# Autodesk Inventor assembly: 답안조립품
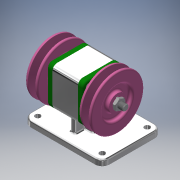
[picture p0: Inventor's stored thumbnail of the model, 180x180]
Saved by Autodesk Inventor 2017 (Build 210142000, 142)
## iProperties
Part Number: 답안조립품
Material: 일반
Document SubType Name: Assembly
Designer: 222
Author: 222
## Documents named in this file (10)
- C:\Users\222\Desktop\김강수\701106V1055\답안조립품.iam
- C:\Users\222\Desktop\김강수\701106V1055\답안본체.ipt
- C:\Users\222\Desktop\김강수\701106V1055\701106V1055\베어링 6004.ipt
- C:\Users\222\Desktop\김강수\701106V1055\701106V1055\축.ipt
- C:\Users\222\Desktop\김강수\701106V1055\701106V1055\커버.ipt
- C:\Users\222\Desktop\김강수\701106V1055\701106V1055\오일 실 17 30 5.ipt
- C:\Users\222\Desktop\김강수\701106V1055\701106V1055\키 5 x 5 x 12.ipt
- C:\Users\222\Desktop\김강수\701106V1055\701106V1055\V-벨트풀리.ipt
- C:\Users\222\Desktop\김강수\701106V1055\701106V1055\너트 M10x1.ipt
- C:\Users\222\Desktop\김강수\701106V1055\701106V1055\볼트 M4.ipt
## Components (2 placed, 1 different names)
1. V-벨트풀리:1
2. V-벨트풀리:2
